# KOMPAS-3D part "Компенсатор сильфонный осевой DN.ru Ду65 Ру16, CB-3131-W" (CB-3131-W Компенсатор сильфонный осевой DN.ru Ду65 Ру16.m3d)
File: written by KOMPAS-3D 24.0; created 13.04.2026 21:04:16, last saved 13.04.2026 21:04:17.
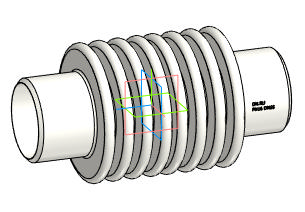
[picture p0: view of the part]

Document properties: Автор: DN.RU; Полное имя файла: D:\PROJECT CAD\DN.RU\...197(ACTUALE). CB-3131-W Компенсатор сильфонный осевой DN.ru\Исходники\DN65\CB-3131-W Компенсатор сильфонный осевой DN.ru Ду65 Ру16.m3d

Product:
- Body: Твердое тело1  | qty 1
    Масса: 1.975447
- Part/product: Компенсатор сильфонный осевой DN.ru Ду65 Ру16  | designation CB-3131-W
    Масса: 1.5
    Раздел спецификации: Прочие изделия
    Комментарий: D140-02122
    Примечание: D140-02122
    additional columns: Типовые

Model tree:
1. Твердое тело1  (labels: Твердое тело1)

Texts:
  CB-3131-W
